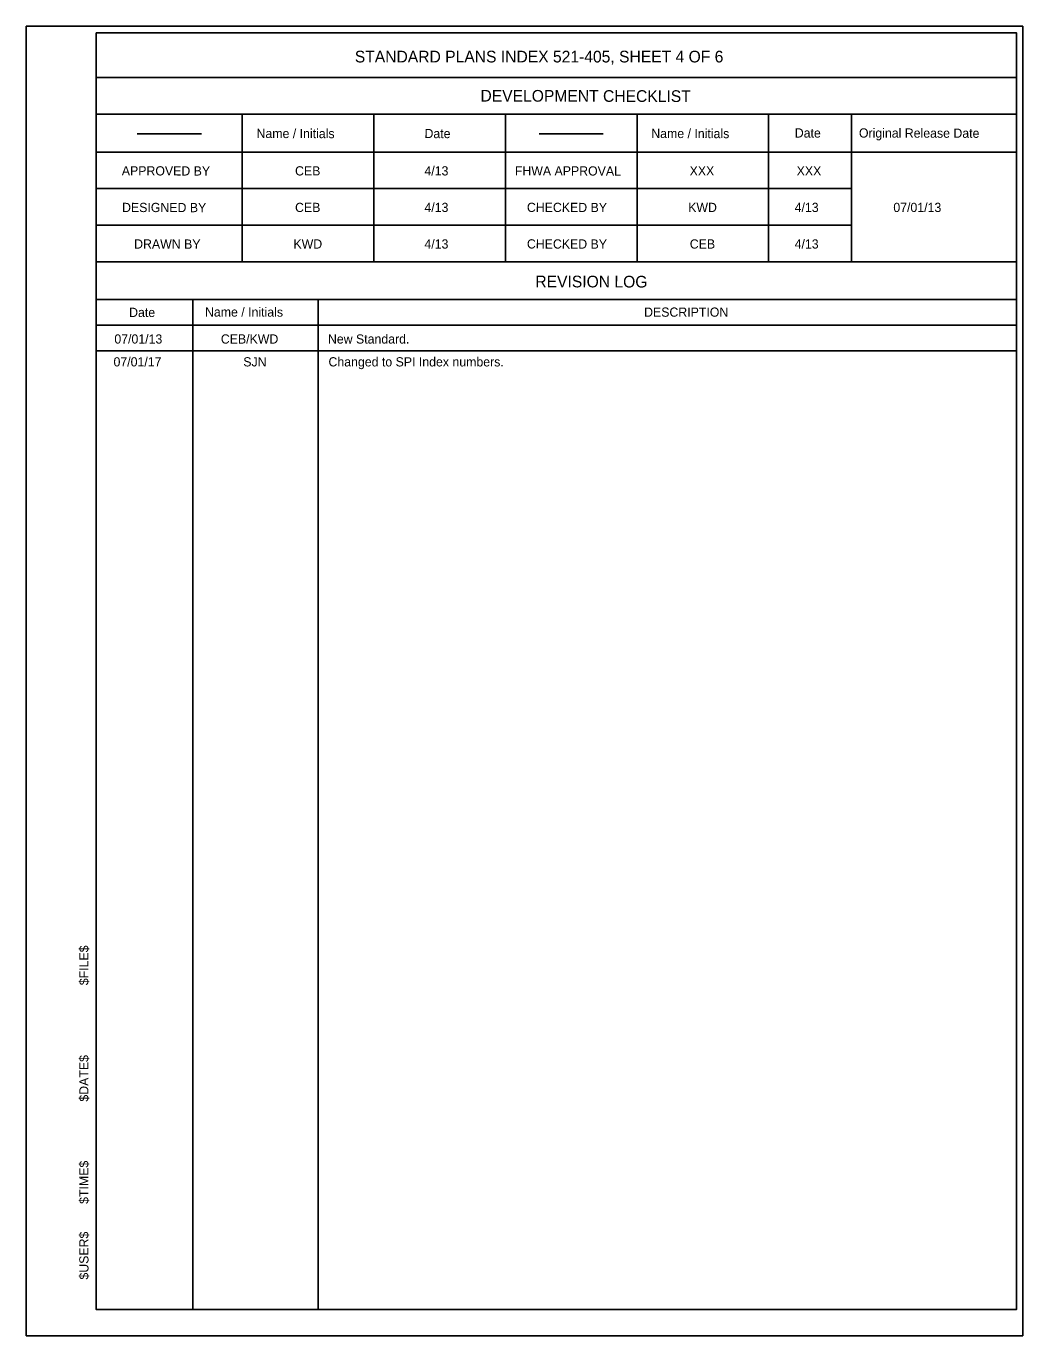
# Model space of a CAD drawing. Extents: x 1.5 to 68.7, y 0 to 31.
# Drawn here: x 46.92 to 68.73, y 0 to 28.67 of the extents above; entities that cross this region are included whole.
import ezdxf

# ---------------------------------------------------------------- set-up
doc = ezdxf.new("R2010")
doc.units = 0
for name, color, linetype in [('AdhocPoint_dp', 7, 'Continuous'), ('Border', 7, 'Continuous'), ('SheetBorder_dp', 7, 'Continuous'), ('TextMisc', 7, 'Continuous')]:
    doc.layers.add(name, color=color, linetype=linetype)

msp = doc.modelspace()

# ---------------------------------------------------------------- linework, layer by layer
at = {"layer": 'AdhocPoint_dp'}
for p, q in [((50.751, 26.312), (49.347, 26.312)), ((59.547, 26.312), (58.144, 26.312))]:
    msp.add_line(p, q, dxfattribs=at)
at = {"layer": 'Border'}
for p, q in [((68.593, 27.54), (48.446, 27.54)), ((68.593, 26.74), (48.446, 26.74)), ((51.646, 26.74), (51.646, 23.512)), ((54.526, 26.74), (54.526, 23.512)), ((57.406, 26.74), (57.406, 23.512)), ((60.286, 26.74), (60.286, 23.512)), ((63.166, 26.74), (63.166, 23.512)), ((64.981, 26.74), (64.981, 23.512)), ((68.593, 25.912), (48.446, 25.912)), ((64.981, 25.112), (48.446, 25.112)), ((64.981, 24.312), (48.446, 24.312)), ((68.593, 23.512), (48.446, 23.512)), ((68.593, 22.684), (48.446, 22.684)), ((50.566, 22.684), (50.566, 0.578)), ((53.309, 22.684), (53.309, 0.578)), ((68.593, 22.121), (48.446, 22.121))]:
    msp.add_line(p, q, dxfattribs=at)
msp.add_lwpolyline([(48.446, 28.521), (68.593, 28.521), (68.593, 0.578), (48.446, 0.578)], close=True, dxfattribs=at)
at = {"layer": 'SheetBorder_dp'}
msp.add_line((46.915, 0), (46.915, 0), dxfattribs=at)
msp.add_lwpolyline([(46.915, 28.667), (68.729, 28.667), (68.729, 0), (46.915, 0)], close=True, dxfattribs=at)
at = {"layer": 'TextMisc'}
msp.add_line((48.446, 21.557), (68.593, 21.557), dxfattribs=at)

# ---------------------------------------------------------------- texts
at = {"layer": 'AdhocPoint_dp'}
msp.add_text('New Standard.', height=0.2016, dxfattribs=at).set_placement((53.52, 21.719))
at = {"layer": 'TextMisc'}
for s, height, p in [('STANDARD PLANS INDEX 521-405, SHEET 4 OF 6', 0.256, (54.108, 27.873)), ('CEB', 0.2016, (52.8, 25.399)), ('4/13', 0.2016, (55.632, 25.399)), ('XXX', 0.2016, (61.436, 25.399)), ('XXX', 0.2016, (63.779, 25.399)), ('CEB', 0.2016, (52.8, 24.599)), ('4/13', 0.2016, (55.632, 24.599)), ('KWD', 0.2016, (61.405, 24.599)), ('4/13', 0.2016, (63.735, 24.599)), ('07/01/13', 0.2016, (65.895, 24.599)), ('KWD', 0.2016, (52.765, 23.799)), ('4/13', 0.2016, (55.632, 23.799)), ('CEB', 0.2016, (61.44, 23.799)), ('4/13', 0.2016, (63.735, 23.799)), ('DESCRIPTION', 0.2016, (60.44, 22.307)), ('07/01/13', 0.2016, (48.845, 21.719)), ('CEB/KWD', 0.2016, (51.176, 21.719)), ('07/01/17', 0.2016, (48.827, 21.219)), ('SJN', 0.2016, (51.667, 21.219)), ('Changed to SPI Index numbers.', 0.2016, (53.532, 21.219))]:
    msp.add_text(s, height=height, dxfattribs=at).set_placement(p)
for s, height, rotation, p in [('DEVELOPMENT CHECKLIST', 0.256, 359.8756, (56.858, 27.017)), ('Name / Initials', 0.2016, 359.8756, (51.957, 26.219)), ('Date', 0.2016, 359.8756, (55.633, 26.217)), ('Name / Initials', 0.2016, 359.8756, (60.597, 26.219)), ('Date', 0.2016, 359.8756, (63.738, 26.229)), ('Original Release Date', 0.2016, 359.8756, (65.142, 26.229)), ('APPROVED BY', 0.2016, 359.8756, (49.008, 25.401)), ('FHWA APPROVAL', 0.2016, 359.8756, (57.611, 25.401)), ('DESIGNED BY', 0.2016, 359.8756, (49.014, 24.599)), ('CHECKED BY', 0.2016, 359.8756, (57.875, 24.601)), ('DRAWN BY', 0.2016, 359.8756, (49.278, 23.799)), ('CHECKED BY', 0.2016, 359.8756, (57.875, 23.801)), ('REVISION LOG', 0.256, 359.8756, (58.059, 22.951)), ('Date', 0.2016, 359.8756, (49.168, 22.302)), ('Name / Initials', 0.2016, 359.8756, (50.829, 22.311)), ('$FILE$', 0.2016, 90, (48.279, 7.675)), ('$DATE$', 0.2016, 90, (48.279, 5.126)), ('$TIME$', 0.2016, 90, (48.279, 2.888)), ('$USER$', 0.2016, 90, (48.279, 1.231))]:
    msp.add_text(s, height=height, rotation=rotation, dxfattribs=at).set_placement(p)

doc.saveas('drawing.dxf')
